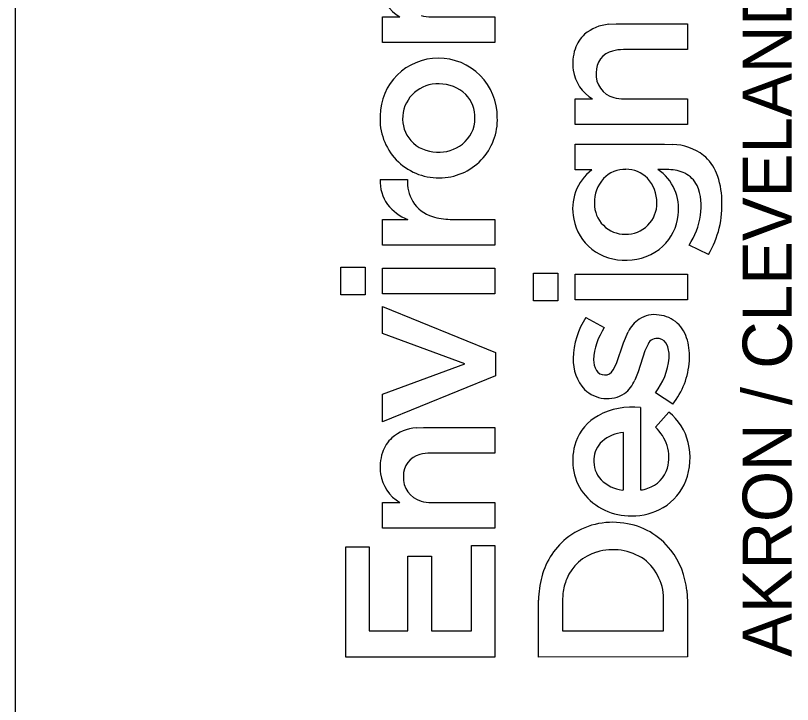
# Model space of a CAD drawing. Extents: x 0 to 34, y 0 to 22.
# Drawn here: x 32 to 32.901, y 2.583 to 3.382 of the extents above; entities that cross this region are included whole.
import ezdxf

# ---------------------------------------------------------------- set-up
doc = ezdxf.new("R2010")
doc.units = 0
doc.layers.add('SC_Scratch1', color=7, linetype='Continuous')
doc.layers.add('SC_Scratch2', color=7, linetype='Continuous')

msp = doc.modelspace()

# ---------------------------------------------------------------- linework, layer by layer
at = {"layer": 'SC_Scratch1'}
msp.add_line((32, 0.5), (32, 21.5), dxfattribs=at)
at = {"layer": 'SC_Scratch2'}
for p, q in [((32.42542, 3.38066), (32.44552, 3.38071)), ((32.42542, 3.35086), (32.42542, 3.38066)), ((32.48222, 3.38071), (32.55569, 3.38071)), ((32.55569, 3.38071), (32.55571, 3.35096)), ((32.68784, 3.3722), (32.69634, 3.37266)), ((32.69634, 3.37266), (32.77916, 3.37266)), ((32.77916, 3.37266), (32.77917, 3.34287)), ((32.55571, 3.35096), (32.42542, 3.35086)), ((32.77917, 3.34287), (32.70485, 3.3428)), ((32.64888, 3.2855), (32.66897, 3.28555)), ((32.64888, 3.25569), (32.64888, 3.2855)), ((32.70568, 3.28555), (32.77915, 3.28555)), ((32.77915, 3.28555), (32.77917, 3.25579)), ((32.77917, 3.25579), (32.64888, 3.25569)), ((32.6489, 3.20336), (32.64889, 3.23322)), ((32.64889, 3.23322), (32.75236, 3.23322)), ((32.75236, 3.23322), (32.76191, 3.23285)), ((32.66836, 3.20336), (32.6489, 3.20336)), ((32.75763, 3.20356), (32.74487, 3.20361)), ((32.42299, 3.19193), (32.45454, 3.19193)), ((32.42542, 3.14577), (32.45473, 3.14579)), ((32.42542, 3.11593), (32.42542, 3.14577)), ((32.50413, 3.14581), (32.55571, 3.14573)), ((32.55571, 3.14573), (32.55565, 3.11593)), ((32.55565, 3.11593), (32.42542, 3.11593)), ((32.8036, 3.10491), (32.7812, 3.11598)), ((32.37705, 3.05818), (32.37705, 3.09026)), ((32.37705, 3.09026), (32.40543, 3.09026)), ((32.40543, 3.09026), (32.40543, 3.05818)), ((32.42542, 3.05942), (32.42542, 3.08928)), ((32.42542, 3.08928), (32.55571, 3.08928)), ((32.55571, 3.08928), (32.55571, 3.05942)), ((32.60051, 3.05111), (32.60051, 3.08319)), ((32.60051, 3.08319), (32.62889, 3.08319)), ((32.62889, 3.08319), (32.62889, 3.05111)), ((32.64888, 3.05234), (32.64888, 3.0822)), ((32.64888, 3.0822), (32.77917, 3.0822)), ((32.77917, 3.0822), (32.77917, 3.05234)), ((32.40543, 3.05818), (32.37705, 3.05818)), ((32.55571, 3.05942), (32.42542, 3.05942)), ((32.62889, 3.05111), (32.60051, 3.05111)), ((32.77917, 3.05234), (32.64888, 3.05234)), ((32.42542, 3.01327), (32.42542, 3.0446)), ((32.42542, 3.0446), (32.5567, 2.9913)), ((32.66151, 3.03207), (32.68268, 3.02025)), ((32.52117, 2.97798), (32.42542, 3.01327)), ((32.70483, 3.00258), (32.71036, 3.01526)), ((32.69675, 2.97868), (32.70483, 3.00258)), ((32.73342, 3.00101), (32.72985, 2.9933)), ((32.5567, 2.9913), (32.5567, 2.96441)), ((32.72985, 2.9933), (32.72213, 2.96882)), ((32.42542, 2.94294), (32.52117, 2.97798)), ((32.69299, 2.97117), (32.69675, 2.97868)), ((32.5567, 2.96441), (32.42542, 2.91086)), ((32.72213, 2.96882), (32.71822, 2.95921)), ((32.42542, 2.91086), (32.42542, 2.94294)), ((32.76214, 2.93141), (32.74198, 2.94469)), ((32.72453, 2.92747), (32.72463, 2.83195)), ((32.74228, 2.90465), (32.75768, 2.922)), ((32.46439, 2.90397), (32.47289, 2.90443)), ((32.47289, 2.90443), (32.55571, 2.90443)), ((32.55571, 2.90443), (32.55571, 2.87465)), ((32.70489, 2.83182), (32.70489, 2.89834)), ((32.55571, 2.87465), (32.4814, 2.87457)), ((32.70361, 2.83165), (32.70489, 2.83182)), ((32.42542, 2.81728), (32.44552, 2.81733)), ((32.42542, 2.78747), (32.42542, 2.81728)), ((32.48222, 2.81733), (32.55569, 2.81733)), ((32.55569, 2.81733), (32.55571, 2.78756)), ((32.55571, 2.78756), (32.42542, 2.78747)), ((32.38298, 2.63791), (32.38298, 2.76598)), ((32.38298, 2.76598), (32.41012, 2.76598)), ((32.41012, 2.76598), (32.41012, 2.66827)), ((32.52857, 2.66827), (32.52857, 2.76722)), ((32.52857, 2.76722), (32.55571, 2.76722)), ((32.55571, 2.76722), (32.55571, 2.63791)), ((32.45503, 2.66827), (32.45503, 2.75488)), ((32.45503, 2.75488), (32.48218, 2.75488)), ((32.48218, 2.75488), (32.48218, 2.66827)), ((32.77847, 2.71497), (32.77917, 2.7021)), ((32.60643, 2.63799), (32.60644, 2.704)), ((32.63465, 2.71178), (32.63407, 2.7023)), ((32.63407, 2.7023), (32.63407, 2.66838)), ((32.75149, 2.66834), (32.75153, 2.70239)), ((32.77917, 2.7021), (32.77917, 2.638)), ((32.41012, 2.66827), (32.45503, 2.66827)), ((32.48218, 2.66827), (32.52857, 2.66827)), ((32.63407, 2.66838), (32.75149, 2.66834)), ((32.55571, 2.63791), (32.38298, 2.63791)), ((32.77917, 2.638), (32.60643, 2.63799))]:
    msp.add_line(p, q, dxfattribs=at)
for points in [[(32.42542, 3.35086), (32.42542, 3.38066), (32.44552, 3.38071)], [(32.48222, 3.38071), (32.55569, 3.38071), (32.55571, 3.35096), (32.42542, 3.35086)], [(32.68784, 3.3722), (32.69634, 3.37266), (32.77916, 3.37266), (32.77917, 3.34287), (32.70485, 3.3428)], [(32.64888, 3.25569), (32.64888, 3.2855), (32.66897, 3.28555)], [(32.70568, 3.28555), (32.77915, 3.28555), (32.77917, 3.25579), (32.64888, 3.25569)], [(32.66836, 3.20336), (32.6489, 3.20336), (32.64889, 3.23322), (32.75236, 3.23322), (32.76191, 3.23285)], [(32.75763, 3.20356), (32.74487, 3.20361)], [(32.42299, 3.19193), (32.45454, 3.19193)], [(32.50413, 3.14581), (32.55571, 3.14573), (32.55565, 3.11593), (32.42542, 3.11593)], [(32.42542, 3.11593), (32.42542, 3.14577), (32.45473, 3.14579)], [(32.8036, 3.10491), (32.7812, 3.11598)], [(32.66151, 3.03207), (32.68268, 3.02025)], [(32.69299, 2.97117), (32.69675, 2.97868), (32.70483, 3.00258), (32.71036, 3.01526)], [(32.73342, 3.00101), (32.72985, 2.9933), (32.72213, 2.96882), (32.71822, 2.95921)], [(32.76214, 2.93141), (32.74198, 2.94469)], [(32.72453, 2.92747), (32.72463, 2.83195)], [(32.74228, 2.90465), (32.75768, 2.922)], [(32.46439, 2.90397), (32.47289, 2.90443), (32.55571, 2.90443), (32.55571, 2.87465), (32.4814, 2.87457)], [(32.70361, 2.83165), (32.70489, 2.83182), (32.70489, 2.89834)], [(32.42542, 2.78747), (32.42542, 2.81728), (32.44552, 2.81733)], [(32.48222, 2.81733), (32.55569, 2.81733), (32.55571, 2.78756), (32.42542, 2.78747)], [(32.77847, 2.71497), (32.77917, 2.7021), (32.77917, 2.638), (32.60643, 2.63799)], [(32.60643, 2.63799), (32.60644, 2.704)], [(32.63465, 2.71178), (32.63407, 2.7023), (32.63407, 2.66838), (32.75149, 2.66834), (32.75153, 2.70239)]]:
    msp.add_lwpolyline(points, dxfattribs=at)
for points in [[(32.37705, 3.05818), (32.37705, 3.09026), (32.40543, 3.09026), (32.40543, 3.05818)], [(32.42542, 3.05942), (32.42542, 3.08928), (32.55571, 3.08928), (32.55571, 3.05942)], [(32.60051, 3.05111), (32.60051, 3.08319), (32.62889, 3.08319), (32.62889, 3.05111)], [(32.64888, 3.05234), (32.64888, 3.0822), (32.77917, 3.0822), (32.77917, 3.05234)], [(32.42542, 2.91086), (32.42542, 2.94294), (32.52117, 2.97798), (32.42542, 3.01327), (32.42542, 3.0446), (32.5567, 2.9913), (32.5567, 2.96441)], [(32.38298, 2.63791), (32.38298, 2.76598), (32.41012, 2.76598), (32.41012, 2.66827), (32.45503, 2.66827), (32.45503, 2.75488), (32.48218, 2.75488), (32.48218, 2.66827), (32.52857, 2.66827), (32.52857, 2.76722), (32.55571, 2.76722), (32.55571, 2.63791)]]:
    msp.add_lwpolyline(points, close=True, dxfattribs=at)
for centre, radius, start, end in [((32.47027, 3.42141), 0.04763, 188.96462, 238.69865), ((32.47027, 3.42141), 0.04763, 188.96462, 238.69865), ((32.48183, 3.42286), 0.04215, 254.08913, 270.52838), ((32.48183, 3.42286), 0.04215, 254.08913, 270.52838), ((32.69216, 3.32251), 0.04988, 94.97056, 130.22484), ((32.69216, 3.32251), 0.04988, 94.97056, 130.22484), ((32.68694, 3.33085), 0.04016, 132.22383, 161.68229), ((32.68694, 3.33085), 0.04016, 132.22383, 161.68229), ((32.70217, 3.32642), 0.05602, 162.27398, 187.79173), ((32.70217, 3.32642), 0.05602, 162.27398, 187.79173), ((32.70453, 3.29679), 0.04601, 89.60515, 105.33026), ((32.70453, 3.29679), 0.04601, 89.60515, 105.33026), ((32.69828, 3.31689), 0.02498, 103.68683, 182.21395), ((32.69828, 3.31689), 0.02498, 103.68683, 182.21395), ((32.49014, 3.26543), 0.0674, 89.84756, 179.64047), ((32.49014, 3.26543), 0.0674, 89.84756, 179.64047), ((32.49057, 3.26474), 0.0681, 359.54009, 90.21138), ((32.49057, 3.26474), 0.0681, 359.54009, 90.21138), ((32.69372, 3.32624), 0.04763, 188.96462, 238.69865), ((32.69372, 3.32624), 0.04763, 188.96462, 238.69865), ((32.7008, 3.31381), 0.02757, 175.58441, 255.13816), ((32.7008, 3.31381), 0.02757, 175.58441, 255.13816), ((32.48923, 3.26263), 0.0404, 87.04809, 175.57259), ((32.48923, 3.26263), 0.0404, 87.04809, 175.57259), ((32.49204, 3.25999), 0.04299, 45.84264, 90.98008), ((32.49204, 3.25999), 0.04299, 45.84264, 90.98008), ((32.49458, 3.26421), 0.03821, 357.88569, 44.15902), ((32.49458, 3.26421), 0.03821, 357.88569, 44.15902), ((32.70529, 3.32769), 0.04215, 254.08913, 270.52838), ((32.70529, 3.32769), 0.04215, 254.08913, 270.52838), ((32.49083, 3.26209), 0.06819, 176.8344, 270.40384), ((32.49083, 3.26209), 0.06819, 176.8344, 270.40384), ((32.48729, 3.2625), 0.03848, 175.15378, 221.14706), ((32.48729, 3.2625), 0.03848, 175.15378, 221.14706), ((32.49123, 3.26139), 0.06749, 270.06243, 2.37759), ((32.49123, 3.26139), 0.06749, 270.06243, 2.37759), ((32.49446, 3.26318), 0.0383, 308.28936, 359.43468), ((32.49446, 3.26318), 0.0383, 308.28936, 359.43468), ((32.48919, 3.26607), 0.04228, 223.09994, 268.80895), ((32.48919, 3.26607), 0.04228, 223.09994, 268.80895), ((32.49096, 3.2679), 0.04418, 266.56515, 308.06078), ((32.49096, 3.2679), 0.04418, 266.56515, 308.06078), ((32.75907, 3.16789), 0.06503, 53.40344, 87.49062), ((32.75907, 3.16789), 0.06503, 53.40344, 87.49062), ((32.76517, 3.18039), 0.05141, 21.60748, 50.5577), ((32.76517, 3.18039), 0.05141, 21.60748, 50.5577), ((32.70292, 3.15813), 0.05692, 127.37482, 192.22468), ((32.70292, 3.15813), 0.05692, 127.37482, 192.22468), ((32.70693, 3.16927), 0.0346, 88.47302, 136.42562), ((32.70693, 3.16927), 0.0346, 88.47302, 136.42562), ((32.70814, 3.16963), 0.03424, 44.27195, 90.47623), ((32.70814, 3.16963), 0.03424, 44.27195, 90.47623), ((32.71421, 3.15829), 0.05472, 352.1125, 55.92295), ((32.71421, 3.15829), 0.05472, 352.1125, 55.92295), ((32.75666, 3.15725), 0.04633, 65.01687, 88.8011), ((32.75666, 3.15725), 0.04633, 65.01687, 88.8011), ((32.7626, 3.17155), 0.03085, 26.26808, 63.80301), ((32.7626, 3.17155), 0.03085, 26.26808, 63.80301), ((32.73069, 3.16714), 0.08835, 1.15143, 21.3627), ((32.73069, 3.16714), 0.08835, 1.15143, 21.3627), ((32.46616, 3.18882), 0.04329, 175.87313, 216.34747), ((32.46616, 3.18882), 0.04329, 175.87313, 216.34747), ((32.50087, 3.18948), 0.04639, 176.9688, 209.60636), ((32.50087, 3.18948), 0.04639, 176.9688, 209.60636), ((32.71141, 3.16602), 0.0401, 137.46739, 182.33237), ((32.71141, 3.16602), 0.0401, 137.46739, 182.33237), ((32.70368, 3.166), 0.03996, 358.57141, 43.53765), ((32.70368, 3.166), 0.03996, 358.57141, 43.53765), ((32.73565, 3.16154), 0.05953, 349.30734, 23.43071), ((32.73565, 3.16154), 0.05953, 349.30734, 23.43071), ((32.47466, 3.19716), 0.05511, 218.09809, 248.7907), ((32.47466, 3.19716), 0.05511, 218.09809, 248.7907), ((32.49514, 3.18814), 0.04079, 211.94466, 253.2028), ((32.49514, 3.18814), 0.04079, 211.94466, 253.2028), ((32.70645, 3.1637), 0.03511, 178.88208, 271.08374), ((32.70645, 3.1637), 0.03511, 178.88208, 271.08374), ((32.70818, 3.16404), 0.03546, 268.27882, 1.55016), ((32.70818, 3.16404), 0.03546, 268.27882, 1.55016), ((32.70538, 3.16244), 0.11383, 329.6388, 3.25998), ((32.70538, 3.16244), 0.11383, 329.6388, 3.25998), ((32.50465, 3.2165), 0.07069, 252.46555, 269.57296), ((32.50465, 3.2165), 0.07069, 252.46555, 269.57296), ((32.70463, 3.15696), 0.05837, 190.75182, 231.28919), ((32.70463, 3.15696), 0.05837, 190.75182, 231.28919), ((32.70988, 3.15708), 0.05887, 313.74196, 353.8554), ((32.70988, 3.15708), 0.05887, 313.74196, 353.8554), ((32.70738, 3.16334), 0.08771, 327.31495, 351.57478), ((32.70738, 3.16334), 0.08771, 327.31495, 351.57478), ((32.70632, 3.16112), 0.06269, 232.46061, 272.59022), ((32.70632, 3.16112), 0.06269, 232.46061, 272.59022), ((32.70954, 3.15901), 0.06051, 269.6361, 312.70877), ((32.70954, 3.15901), 0.06051, 269.6361, 312.70877), ((32.73636, 2.98258), 0.08973, 146.53104, 178.7571), ((32.73636, 2.98258), 0.08973, 146.53104, 178.7571), ((32.74661, 2.99713), 0.04053, 125.51182, 153.41595), ((32.74661, 2.99713), 0.04053, 125.51182, 153.41595), ((32.7406, 3.0026), 0.03263, 80.17192, 122.51969), ((32.7406, 3.0026), 0.03263, 80.17192, 122.51969), ((32.74278, 2.99824), 0.03667, 47.79344, 84.68918), ((32.74278, 2.99824), 0.03667, 47.79344, 84.68918), ((32.74519, 2.9789), 0.07495, 146.51121, 176.91007), ((32.74519, 2.9789), 0.07495, 146.51121, 176.91007), ((32.73788, 2.9946), 0.04267, 14.9966, 46.20632), ((32.73788, 2.9946), 0.04267, 14.9966, 46.20632), ((32.74384, 2.99631), 0.01143, 76.66094, 155.7053), ((32.74384, 2.99631), 0.01143, 76.66094, 155.7053), ((32.74397, 2.99511), 0.01256, 21.5098, 78.52618), ((32.74397, 2.99511), 0.01256, 21.5098, 78.52618), ((32.71044, 2.98674), 0.07121, 355.83062, 15.39138), ((32.71044, 2.98674), 0.07121, 355.83062, 15.39138), ((32.72592, 2.98766), 0.03209, 354.57264, 22.06805), ((32.72592, 2.98766), 0.03209, 354.57264, 22.06805), ((32.69666, 2.98238), 0.05005, 177.53659, 222.79318), ((32.69666, 2.98238), 0.05005, 177.53659, 222.79318), ((32.6931, 2.98233), 0.02276, 178.47474, 211.08679), ((32.6931, 2.98233), 0.02276, 178.47474, 211.08679), ((32.68248, 2.99149), 0.0757, 321.81101, 354.79685), ((32.68248, 2.99149), 0.0757, 321.81101, 354.79685), ((32.68952, 2.9882), 0.09219, 321.9777, 355.87384), ((32.68952, 2.9882), 0.09219, 321.9777, 355.87384), ((32.68331, 2.9767), 0.01148, 212.23676, 268.37769), ((32.68331, 2.9767), 0.01148, 212.23676, 268.37769), ((32.68342, 2.97589), 0.01067, 267.71603, 333.73375), ((32.68342, 2.97589), 0.01067, 267.71603, 333.73375), ((32.68098, 2.9758), 0.04077, 308.08772, 335.98736), ((32.68098, 2.9758), 0.04077, 308.08772, 335.98736), ((32.68599, 2.97535), 0.0375, 225.98539, 302.47965), ((32.68599, 2.97535), 0.0375, 225.98539, 302.47965), ((32.7152, 2.84414), 0.08384, 83.61499, 118.28755), ((32.7152, 2.84414), 0.08384, 83.61499, 118.28755), ((32.71744, 2.87167), 0.06443, 13.53365, 51.36148), ((32.71744, 2.87167), 0.06443, 13.53365, 51.36148), ((32.70239, 2.86906), 0.05583, 118.83082, 160.62438), ((32.70239, 2.86906), 0.05583, 118.83082, 160.62438), ((32.46871, 2.85428), 0.04988, 94.96958, 130.22249), ((32.46871, 2.85428), 0.04988, 94.96958, 130.22249), ((32.70378, 2.86556), 0.05486, 19.03571, 45.44059), ((32.70378, 2.86556), 0.05486, 19.03571, 45.44059), ((32.46348, 2.86263), 0.04015, 132.22192, 161.68183), ((32.46348, 2.86263), 0.04015, 132.22192, 161.68183), ((32.70785, 2.85609), 0.04235, 94.00805, 130.88169), ((32.70785, 2.85609), 0.04235, 94.00805, 130.88169), ((32.71041, 2.86612), 0.06437, 160.52012, 215.78311), ((32.71041, 2.86612), 0.06437, 160.52012, 215.78311), ((32.70048, 2.86628), 0.02985, 132.98507, 177.179), ((32.70048, 2.86628), 0.02985, 132.98507, 177.179), ((32.71069, 2.8697), 0.047, 344.60586, 17.007), ((32.71069, 2.8697), 0.047, 344.60586, 17.007), ((32.70635, 2.86921), 0.07579, 339.3542, 13.37853), ((32.70635, 2.86921), 0.07579, 339.3542, 13.37853), ((32.47872, 2.85819), 0.05601, 162.27355, 187.79185), ((32.47872, 2.85819), 0.05601, 162.27355, 187.79185), ((32.48108, 2.82856), 0.04601, 89.60494, 105.3284), ((32.48108, 2.82856), 0.04601, 89.60494, 105.3284), ((32.47482, 2.84867), 0.02498, 103.68646, 182.21874), ((32.47482, 2.84867), 0.02498, 103.68646, 182.21874), ((32.7017, 2.86503), 0.03115, 175.00126, 223.28301), ((32.7017, 2.86503), 0.03115, 175.00126, 223.28301), ((32.7224, 2.86715), 0.03504, 288.00773, 343.55078), ((32.7224, 2.86715), 0.03504, 288.00773, 343.55078), ((32.47026, 2.85802), 0.04762, 188.96199, 238.70369), ((32.47026, 2.85802), 0.04762, 188.96199, 238.70369), ((32.47735, 2.84558), 0.02756, 175.58538, 255.14386), ((32.47735, 2.84558), 0.02756, 175.58538, 255.14386), ((32.70891, 2.87363), 0.04231, 225.06188, 262.79738), ((32.70891, 2.87363), 0.04231, 225.06188, 262.79738), ((32.71894, 2.8652), 0.0626, 300.94269, 338.73225), ((32.71894, 2.8652), 0.0626, 300.94269, 338.73225), ((32.72474, 2.85216), 0.02021, 269.7003, 294.8711), ((32.72474, 2.85216), 0.02021, 269.7003, 294.8711), ((32.71253, 2.87054), 0.06872, 217.74516, 271.65431), ((32.71253, 2.87054), 0.06872, 217.74516, 271.65431), ((32.48183, 2.85948), 0.04215, 254.09162, 270.52835), ((32.48183, 2.85948), 0.04215, 254.09162, 270.52835), ((32.71549, 2.87241), 0.07056, 269.20477, 300.33412), ((32.71549, 2.87241), 0.07056, 269.20477, 300.33412), ((32.69229, 2.70792), 0.08641, 81.19402, 125.99844), ((32.69229, 2.70792), 0.08641, 81.19402, 125.99844), ((32.69458, 2.71132), 0.08272, 37.85208, 82.40204), ((32.69458, 2.71132), 0.08272, 37.85208, 82.40204), ((32.69387, 2.70893), 0.08654, 127.23621, 165.14796), ((32.69387, 2.70893), 0.08654, 127.23621, 165.14796), ((32.68893, 2.70782), 0.05398, 106.18808, 157.38609), ((32.68893, 2.70782), 0.05398, 106.18808, 157.38609), ((32.69279, 2.69862), 0.06389, 55.67272, 107.20935), ((32.69279, 2.69862), 0.06389, 55.67272, 107.20935), ((32.68586, 2.70567), 0.09308, 5.73329, 37.30396), ((32.68586, 2.70567), 0.09308, 5.73329, 37.30396), ((32.69291, 2.70499), 0.05867, 357.46616, 52.26647), ((32.69291, 2.70499), 0.05867, 357.46616, 52.26647), ((32.71426, 2.70281), 0.10783, 164.7861, 179.37039), ((32.71426, 2.70281), 0.10783, 164.7861, 179.37039), ((32.69829, 2.70389), 0.06412, 157.35705, 172.92755), ((32.69829, 2.70389), 0.06412, 157.35705, 172.92755)]:
    msp.add_arc(centre, radius, start, end, dxfattribs=at)

# ---------------------------------------------------------------- texts
msp.add_text('AKRON / CLEVELAND / COLUMBUS', height=0.056969, rotation=90, dxfattribs=at).set_placement((32.90012, 2.638))

doc.saveas('drawing.dxf')
